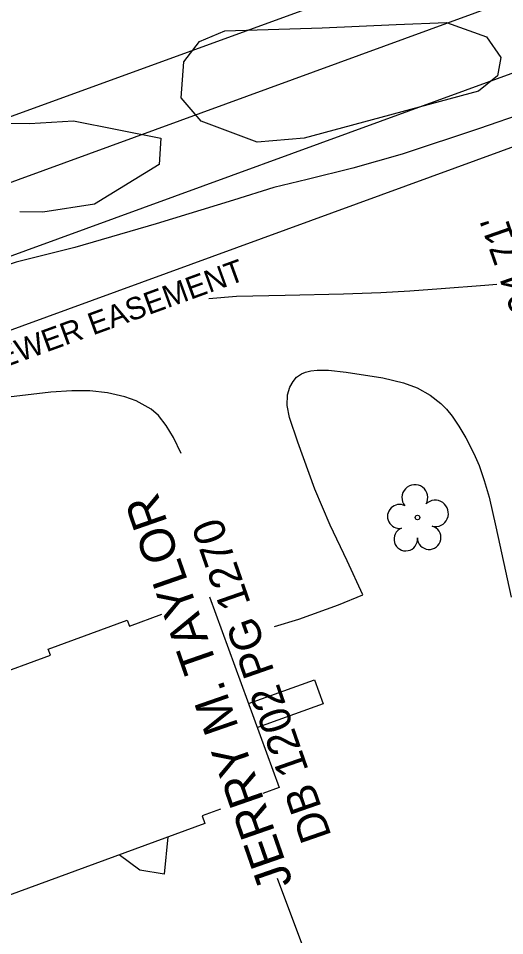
# Model space of a CAD drawing. Extents: x 1614427 to 1617186, y 896524 to 905462.
# Drawn here: x 1616476.2 to 1616546.3, y 903503 to 903635.2 of the extents above; entities that cross this region are included whole.
import ezdxf

# ---------------------------------------------------------------- set-up
doc = ezdxf.new("R2010")
doc.units = 0
for name, color, linetype in [('Exist Building', 7, 'Continuous'), ('Exist Other Culture Area Outline', 7, 'Continuous'), ('Exist Other Culture Fence Line', 7, 'Continuous'), ('Exist Property Deed Book Text', 7, 'Continuous'), ('Exist Property Owner Text', 7, 'Continuous'), ('Exist Right of Way Easement Line', 7, 'Continuous'), ('Exist Right of Way Easement Line Text', 7, 'Continuous'), ('Exist Right of Way Line', 7, 'Continuous'), ('Exist Roads Soil', 7, 'Continuous'), ('Exist Utilities Sanitary Sewer Manhole Text', 7, 'Continuous'), ('Exist Utilities Sanitary Sewer UG Line', 7, 'Continuous'), ('Exist Vegetation Tree CELL', 7, 'Continuous'), ('Exist Vegetation Woods Line', 7, 'Continuous')]:
    doc.layers.add(name, color=color, linetype=linetype)

msp = doc.modelspace()

# ---------------------------------------------------------------- linework, layer by layer
at = {"layer": 'Exist Building'}
for points in [[(1616503.77, 903551.86), (1616513.84, 903524.37), (1616511.45, 903523.5)], [(1616505.37, 903521.27), (1616502.73, 903520.3), (1616503.12, 903519.21), (1616464.68, 903505.13), (1616462.02, 903512.38), (1616455.15, 903509.86), (1616449.95, 903524.07), (1616456.72, 903526.55), (1616454.12, 903533.64), (1616480.87, 903543.44), (1616480.54, 903544.32), (1616491.93, 903548.49), (1616492.25, 903547.63), (1616496.91, 903549.34)]]:
    msp.add_lwpolyline(points, dxfattribs=at)
at = {"layer": 'Exist Other Culture Area Outline'}
msp.add_lwpolyline([(1616509.41, 903536.46), (1616518.9, 903539.9), (1616520.15, 903536.44), (1616510.68, 903533)], dxfattribs=at)
at = {"layer": 'Exist Other Culture Fence Line'}
for points in [[(1616572.91, 903628.18), (1616564.21, 903625.69), (1616557.86, 903623.87), (1616549.37, 903621.59), (1616542.69, 903619.31), (1616531.55, 903615.59), (1616524.44, 903613.58), (1616517.86, 903611.96), (1616513.04, 903610.8), (1616507.24, 903608.97), (1616496.07, 903605.56), (1616484.35, 903602.15), (1616475.89, 903600.04), (1616461.24, 903595.28), (1616451.31, 903592.92), (1616438.36, 903588.93), (1616423.69, 903584.65), (1616405.19, 903578.96)], [(1616497.76, 903517.25), (1616497.26, 903511.88), (1616493.75, 903512.45), (1616490.77, 903514.69)], [(1616418.3, 903503.27), (1616425.66, 903480.85), (1616434.72, 903450.26), (1616469.04, 903462.52), (1616499.54, 903473.23), (1616524.45, 903482.31), (1616513.56, 903511.28)]]:
    msp.add_lwpolyline(points, dxfattribs=at)
at = {"layer": 'Exist Right of Way Easement Line'}
for p, q in [((1616390.19, 903580.61), (1616545.12, 903637.08)), ((1616389.05, 903558.9), (1616562.68, 903622.19))]:
    msp.add_line(p, q, dxfattribs=at)
at = {"layer": 'Exist Right of Way Line'}
msp.add_line((1616407.32, 903596.49), (1616537.09, 903643.56), dxfattribs=at)
at = {"layer": 'Exist Roads Soil'}
for points in [[(1616545.21, 903596.85), (1616543.48, 903596.71), (1616537.18, 903596.2), (1616532.68, 903595.88), (1616528.46, 903595.65), (1616523.1, 903595.46), (1616514.71, 903595.24), (1616507.67, 903595.1), (1616503.68, 903594.76)], [(1616513.15, 903547.56), (1616516.66, 903548.6), (1616522.38, 903550.7), (1616525.87, 903552.15), (1616523.61, 903557.02), (1616521.16, 903562.15), (1616518.95, 903567.34), (1616516.53, 903574.1), (1616515.32, 903577.68), (1616514.99, 903579.39), (1616515.01, 903580.94), (1616515.36, 903582.03), (1616515.83, 903582.87), (1616516.34, 903583.48), (1616517.02, 903583.95), (1616517.63, 903584.21), (1616518.41, 903584.41), (1616519.29, 903584.47), (1616520.95, 903584.47), (1616523.49, 903584.18), (1616528.77, 903583.4), (1616531.73, 903582.68), (1616533.71, 903581.96), (1616535.6, 903580.88), (1616537.12, 903579.7), (1616537.94, 903578.85), (1616538.76, 903577.87), (1616539.71, 903576.42), (1616540.74, 903574.73), (1616541.89, 903572.47), (1616542.66, 903570.77), (1616543.4, 903568.59), (1616544.08, 903566.18), (1616545.06, 903561.94), (1616547.27, 903551.79)], [(1616499.67, 903572.5), (1616498.59, 903574.77), (1616497.54, 903576.52), (1616496.43, 903577.96), (1616495.38, 903578.86), (1616493.21, 903580.08), (1616491.58, 903580.65), (1616489.07, 903581.25), (1616486.53, 903581.51), (1616483.91, 903581.53), (1616480.9, 903581.3), (1616472.29, 903580.3), (1616465.03, 903579.16), (1616459.27, 903578.05), (1616454.38, 903576.9), (1616447.04, 903575.01), (1616441.58, 903573.34), (1616435.76, 903571.37), (1616430.37, 903569.45), (1616426.35, 903567.9)]]:
    msp.add_lwpolyline(points, dxfattribs=at)
at = {"layer": 'Exist Utilities Sanitary Sewer UG Line'}
msp.add_line((1616396.73, 903572.35), (1616553.9, 903629.64), dxfattribs=at)
at = {"layer": 'Exist Vegetation Tree CELL'}
msp.add_line((1616533.77, 903563.27), (1616533.77, 903563.27), dxfattribs=at)
msp.add_circle((1616533.77, 903563.27), 0.326, dxfattribs=at)
for centre, radius, start, end in [((1616533.39, 903566.14), 1.86, 330.1651, 219.7134), ((1616536.32, 903563.86), 1.9, 257.1011, 134.1999), ((1616531.17, 903563.42), 1.73, 62.6636, 279.3457), ((1616532.07, 903560.15), 1.69, 111.5671, 6.231), ((1616535.45, 903560.37), 1.7, 181.2822, 74.56)]:
    msp.add_arc(centre, radius, start, end, dxfattribs=at)
at = {"layer": 'Exist Vegetation Woods Line'}
for points in [[(1616505.99, 903633.38), (1616520, 903633.79), (1616530.67, 903634.28), (1616537.97, 903634.59), (1616543.73, 903632.51), (1616545.78, 903629.52), (1616545.29, 903626.9), (1616542.57, 903624.66), (1616517.42, 903617.91), (1616510.65, 903617.32), (1616502.57, 903620.35), (1616499.67, 903623.73), (1616500.06, 903628.91), (1616502.35, 903631.84), (1616505.99, 903633.38)], [(1616432.8, 903609.03), (1616439.6, 903609.78), (1616452, 903614.86), (1616457.45, 903616.76), (1616471.15, 903620.1), (1616477.81, 903620.04), (1616484.16, 903620.42), (1616496.78, 903617.93), (1616496.52, 903614.11), (1616487.2, 903608.39), (1616479.77, 903607.27), (1616476.43, 903607.29)]]:
    msp.add_lwpolyline(points, dxfattribs=at)

# ---------------------------------------------------------------- texts
at = {"layer": 'Exist Property Deed Book Text'}
msp.add_text('DB 1202 PG 1270', height=4.5, rotation=109.1768, dxfattribs=at).set_placement((1616521.41, 903517.4))
at = {"layer": 'Exist Property Owner Text'}
msp.add_text('JERRY M. TAYLOR', height=5, rotation=109.1768, dxfattribs=at).set_placement((1616515.84, 903510.62))
at = {"layer": 'Exist Right of Way Easement Line Text'}
msp.add_text("20' SEWER EASEMENT", height=3.2, rotation=20.0264, dxfattribs=at).set_placement((1616464.75, 903581.39))
at = {"layer": 'Exist Utilities Sanitary Sewer Manhole Text'}
msp.add_text("TOP=994.71'", height=4, rotation=109.1768, dxfattribs=at).set_placement((1616556.82, 903577.44))

doc.saveas('drawing.dxf')
